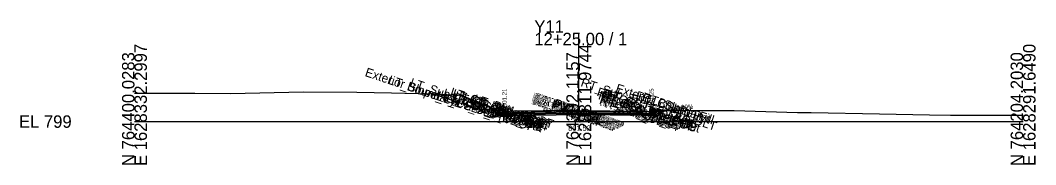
# Model space of a CAD drawing. Extents: x -26 to 203, y -10 to 6017.
# Drawn here: x -25.7 to 202.8, y 4490.3 to 4522.8 of the extents above; entities that cross this region are included whole.
import ezdxf

# ---------------------------------------------------------------- set-up
doc = ezdxf.new("R2010")
doc.units = 0
for name, color, linetype in [('Default', 7, 'Continuous'), ('Exist Cross Section Cell', 7, 'Continuous'), ('Exist XS Center Line Elevation Label', 7, 'Continuous'), ('Exist XS Ground Line', 7, 'Continuous'), ('Prop CMT Conc Surface', 7, 'Continuous'), ('Prop CMT Concrete Structures', 7, 'Continuous'), ('Prop CMT Pvmt Course 1', 7, 'Continuous'), ('Prop CMT Pvmt Course 1 CG', 7, 'Continuous'), ('Prop CMT Pvmt Course 2', 7, 'Continuous'), ('Prop CMT Pvmt Course 3', 7, 'Continuous'), ('Prop CMT Pvmt Surface', 7, 'Continuous'), ('Prop CMT Pvmt Wedge Surface 1', 7, 'Continuous'), ('Prop CMT Pvmt Wedge Surface 2', 7, 'Continuous'), ('Prop CMT Pvmt Wedge Surface 3', 7, 'Continuous'), ('Prop CMT Slope Grass', 7, 'Continuous'), ('Prop CMT Subgrade Earthwork', 7, 'Continuous'), ('Prop XS Hydro Elevations', 7, 'Continuous'), ('Prop XS SE Text', 7, 'Continuous'), ('Prop XS Side Slope Text', 7, 'Continuous'), ('Scratch_Level_0', 7, 'Continuous')]:
    doc.layers.add(name, color=color, linetype=linetype)

msp = doc.modelspace()

# ---------------------------------------------------------------- linework, layer by layer
at = {"layer": 'Exist Cross Section Cell'}
for p, q in [((100, 4500), (100, 4519.98)), ((0, 4500), (100, 4500)), ((100, 4500), (200, 4500))]:
    msp.add_line(p, q, dxfattribs=at)
at = {"layer": 'Exist XS Ground Line'}
msp.add_lwpolyline([(0, 4506.39), (13.6, 4506.36), (21.72, 4506.33), (37.96, 4506.66), (50.03, 4506.61), (57.82, 4506.48), (66.83, 4506.23), (73.58, 4505.91), (82.43, 4502.12), (85.02, 4501.87), (93.51, 4502.52), (94.84, 4502.6), (97.67, 4502.56), (100, 4502.52), (115.54, 4502.24), (116.78, 4502.48), (117.29, 4502.53), (118.78, 4502.66), (127.08, 4502.47), (130.69, 4502.46), (134.95, 4502.46), (149.2, 4502.02), (152.32, 4502.02), (167.7, 4501.71), (178.97, 4501.49), (183.66, 4501.43), (184.51, 4501.41), (200, 4501.43)], dxfattribs=at)
at = {"layer": 'Prop CMT Conc Surface'}
for points in [[(83.29, 4502.21), (83.29, 4502.71), (82.79, 4502.71)], [(85.28, 4502.31), (83.29, 4502.21)], [(114.38, 4502.35), (116.37, 4502.25)]]:
    msp.add_lwpolyline(points, dxfattribs=at)
at = {"layer": 'Prop CMT Concrete Structures'}
for p, q in [((116.37, 4502.25), (116.87, 4502.36)), ((116.87, 4502.36), (121.87, 4502.46)), ((121.87, 4502.46), (123.89, 4502.54))]:
    msp.add_line(p, q, dxfattribs=at)
for points in [[(85.28, 4502.31), (83.29, 4502.21), (83.29, 4502.71), (82.79, 4502.71)], [(82.79, 4502.71), (82.8, 4501.7), (85.28, 4501.73)], [(85.28, 4501.73), (85.28, 4502.31)], [(116.86, 4502.36), (116.86, 4501.74), (114.38, 4501.77)], [(114.38, 4501.77), (114.38, 4502.35)], [(114.38, 4502.35), (116.37, 4502.25)]]:
    msp.add_lwpolyline(points, dxfattribs=at)
at = {"layer": 'Prop CMT Pvmt Course 1'}
for points in [[(99.75, 4502.5), (85.28, 4502.31)], [(85.28, 4502.31), (85.28, 4502.06)], [(85.28, 4502.06), (99.75, 4502.25)], [(99.75, 4502.25), (99.75, 4502.5)], [(99.75, 4502.5), (114.38, 4502.35)], [(99.75, 4502.25), (99.75, 4502.5)], [(114.38, 4502.1), (99.75, 4502.25)], [(114.38, 4502.35), (114.38, 4502.1)]]:
    msp.add_lwpolyline(points, dxfattribs=at)
msp.add_lwpolyline([(99.75, 4502.25), (99.75, 4502.37), (99.75, 4502.37), (99.75, 4502.25)], close=True, dxfattribs=at)
msp.add_lwpolyline([(99.75, 4502.25), (99.75, 4502.37), (99.75, 4502.37), (99.75, 4502.25)], close=True, dxfattribs=at)
at = {"layer": 'Prop CMT Pvmt Course 1 CG'}
for points in [[(85.28, 4501.73), (82.3, 4501.69), (81.96, 4501.35)], [(81.96, 4501.35), (85.28, 4501.39)], [(85.28, 4501.39), (85.28, 4501.73)], [(114.38, 4501.77), (117.36, 4501.74), (117.7, 4501.4)], [(114.38, 4501.43), (114.38, 4501.77)], [(117.7, 4501.4), (114.38, 4501.43)]]:
    msp.add_lwpolyline(points, dxfattribs=at)
at = {"layer": 'Prop CMT Pvmt Course 2'}
for points in [[(99.75, 4502.25), (85.28, 4502.06)], [(99.75, 4501.91), (99.75, 4502.25)], [(99.75, 4501.91), (99.75, 4502.25)], [(99.75, 4502.25), (114.38, 4502.1)], [(99.75, 4502.25), (99.75, 4502.25)], [(99.75, 4502.25), (99.75, 4502.25)], [(114.38, 4502.1), (114.38, 4501.77)], [(85.28, 4502.06), (85.28, 4501.73)], [(85.28, 4501.73), (99.75, 4501.91)], [(114.38, 4501.77), (99.75, 4501.91)]]:
    msp.add_lwpolyline(points, dxfattribs=at)
msp.add_lwpolyline([(99.75, 4502.25), (99.75, 4501.91), (99.75, 4501.91)], close=True, dxfattribs=at)
msp.add_lwpolyline([(99.75, 4502.25), (99.75, 4501.91), (99.75, 4501.91)], close=True, dxfattribs=at)
at = {"layer": 'Prop CMT Pvmt Course 3'}
for points in [[(99.75, 4501.91), (85.28, 4501.73)], [(85.28, 4501.73), (85.28, 4501.39)], [(85.28, 4501.39), (99.75, 4501.58)], [(99.75, 4501.58), (99.75, 4501.91)], [(99.75, 4501.91), (114.38, 4501.77)], [(99.75, 4501.58), (99.75, 4501.91)], [(99.75, 4501.91), (99.75, 4501.91), (99.75, 4501.58), (99.75, 4501.58)], [(99.75, 4501.58), (99.75, 4501.91)], [(99.75, 4501.91), (99.75, 4501.91), (99.75, 4501.58), (99.75, 4501.58)], [(99.75, 4501.58), (99.75, 4501.91)], [(114.38, 4501.43), (99.75, 4501.58)], [(114.38, 4501.77), (114.38, 4501.43)]]:
    msp.add_lwpolyline(points, dxfattribs=at)
at = {"layer": 'Prop CMT Pvmt Surface'}
for points in [[(99.75, 4502.5), (85.28, 4502.31)], [(99.75, 4502.5), (114.38, 4502.35)]]:
    msp.add_lwpolyline(points, dxfattribs=at)
at = {"layer": 'Prop CMT Pvmt Wedge Surface 1'}
for points in [[(99.75, 4502.5), (99.75, 4502.25), (99.75, 4502.25)], [(99.75, 4502.5), (99.75, 4502.25), (99.75, 4502.25)], [(99.75, 4502.25), (99.75, 4502.37)], [(99.75, 4502.25), (99.75, 4502.37)]]:
    msp.add_lwpolyline(points, dxfattribs=at)
at = {"layer": 'Prop CMT Pvmt Wedge Surface 2'}
for points in [[(99.75, 4502.5), (99.75, 4502.25)], [(99.75, 4502.5), (99.75, 4502.25)], [(99.75, 4502.25), (99.75, 4502.25)], [(99.75, 4502.25), (99.75, 4502.25)]]:
    msp.add_lwpolyline(points, dxfattribs=at)
at = {"layer": 'Prop CMT Pvmt Wedge Surface 3'}
for points in [[(99.75, 4502.5), (99.75, 4501.91)], [(99.75, 4502.5), (99.75, 4501.91)], [(99.75, 4501.91), (99.75, 4501.91)], [(99.75, 4501.91), (99.75, 4501.91)]]:
    msp.add_lwpolyline(points, dxfattribs=at)
at = {"layer": 'Prop CMT Slope Grass'}
msp.add_lwpolyline([(82.79, 4502.71), (77.32, 4502.82), (67.07, 4506.22)], dxfattribs=at)
at = {"layer": 'Prop CMT Subgrade Earthwork'}
for points in [[(85.28, 4501.39), (81.96, 4501.35), (80.57, 4502.75)], [(114.38, 4501.43), (117.7, 4501.4), (118.69, 4502.4)], [(99.75, 4501.58), (85.28, 4501.39)], [(99.75, 4501.58), (114.38, 4501.43)]]:
    msp.add_lwpolyline(points, dxfattribs=at)

# ---------------------------------------------------------------- texts
at = {"layer": 'Default'}
msp.add_text('-', height=0.0001, dxfattribs=at).set_placement((0, 4500))
at = {"layer": 'Exist Cross Section Cell'}
for s, p in [('Y11', (90, 4519.98)), ('12+25.00 / 1', (90, 4517.18)), ('EL 799', (-26, 4498.6))]:
    msp.add_text(s, height=2.8, dxfattribs=at).set_placement(p)
for s, p in [('E 1628332.2997', (2.8, 4490)), ('E 1628311.9744', (102.8, 4490)), ('E 1628291.6490', (202.8, 4490)), ('N 764400.0283', (0, 4490)), ('N 764302.1157', (100, 4490)), ('N 764204.2030', (200, 4490))]:
    msp.add_text(s, height=2.8, rotation=90, dxfattribs=at).set_placement(p)
at = {"layer": 'Exist XS Center Line Elevation Label'}
msp.add_text('801.52', height=1.2, dxfattribs=at).set_placement((97.62, 4497.92))
at = {"layer": 'Prop XS Hydro Elevations'}
for s, p in [('801.21', (83.79, 4503.21)), ('801.25', (116.87, 4503.25))]:
    msp.add_text(s, height=1, rotation=90, dxfattribs=at).set_placement(p)
at = {"layer": 'Prop XS SE Text'}
for s, rotation, p in [('0.013', 0.7308, (90.9, 4503.38)), ('0.010', 359.4297, (105.44, 4503.44)), ('2.00%', 1.1458, (117.67, 4502.55)), ('4.00%', 2.2906, (121.89, 4502.71))]:
    msp.add_text(s, height=1, rotation=rotation, dxfattribs=at).set_placement(p)
at = {"layer": 'Prop XS Side Slope Text'}
msp.add_text('3:1', height=1, rotation=341.6367, dxfattribs=at).set_placement((71.69, 4505.47))
at = {"layer": 'Scratch_Level_0'}
for s, p in [('Exterior Boundary', (51.73, 4510.28)), ('LT_Slope_Cut', (56.94, 4508.54)), ('LT_Sub_Trench_Out_DLT', (61.82, 4507.95)), ('RT_Sub_Trench_Out_DLT', (100.29, 4508.01)), ('LT_CSLP_Pnt', (67.68, 4504.97)), ('LT_CG1_Shelf_Out', (69.22, 4504.99)), ('LT_CG_Top_Face', (70.89, 4505.79)), ('LT_CG_Top_BOC', (71.36, 4505.46)), ('LT_CG_Top_Gut', (71.82, 4504.98)), ('RT_CG_Top_Face', (103.92, 4505.85)), ('RT_CG1_Shelf_Out', (104.24, 4505.06)), ('RT_CG_Top_Gut', (104.84, 4505.04)), ('RT_CG_Top_BOC', (105.39, 4505.52)), ('Exterior Boundary', (108.12, 4506.67)), ('RT_CSLP_Pnt', (112.65, 4505.03)), ('LT_CG_Bot_BOC', (71.39, 4504.44)), ('LT_Sub_OEOP', (72.26, 4503.53)), ('LT_CG_Bot_IE', (75.4, 4503.97)), ('LT_Sub_OEOT', (75.55, 4503.58)), ('LT_PV2_OEOT', (75.64, 4504.22)), ('LT_PV3_OEOT', (75.64, 4503.89)), ('LT_PV1_OEOT', (76.18, 4504.29)), ('RT_Sub_OEEOP', (89.16, 4504.06)), ('LT_Sub_OEEOP', (89.2, 4504.04)), ('RT_PV2_OEEOP', (89.25, 4504.69)), ('RT_PV3_OEEOP', (89.25, 4504.36)), ('LT_PV2_OEEOP', (89.29, 4504.68)), ('LT_PV3_OEEOP', (89.29, 4504.35)), ('RT_Sub_IEEOP', (89.77, 4503.85)), ('RT_PV1_OEEOP', (89.78, 4504.64)), ('LT_Sub_IEEOP', (89.81, 4503.84)), ('LT_PV1_OEEOP', (89.83, 4504.62)), ('RT_PV2_IEEOP', (89.86, 4504.49)), ('RT_PV3_IEEOP', (89.86, 4504.16)), ('LT_PV2_IEEOP', (89.9, 4504.47)), ('LT_PV3_IEEOP', (89.9, 4504.14)), ('RT_PV1_IEEOP', (90.4, 4504.43)), ('LT_PV1_IEEOP', (90.44, 4504.42)), ('PV2_PGL', (93.65, 4503.22)), ('PV3_PGL', (93.65, 4502.89)), ('PV1_PGL', (94.19, 4503.3)), ('RT_CG_Bot_IE', (104.45, 4504.02)), ('RT_Sub_OEOT', (104.6, 4503.64)), ('RT_PV2_OEOT', (104.69, 4504.27)), ('RT_PV3_OEOT', (104.69, 4503.94)), ('RT_PV1_OEOT', (105.23, 4504.34)), ('RT_CG_Bot_BOC', (105.42, 4504.5)), ('RT_Sub_OEOP', (107.95, 4503.59)), ('RT_Slope_Fill', (114.12, 4504.67)), ('Sub_PGL', (93.56, 4502.59))]:
    msp.add_text(s, height=2, rotation=341.5651, dxfattribs=at).set_placement(p)

doc.saveas('drawing.dxf')
